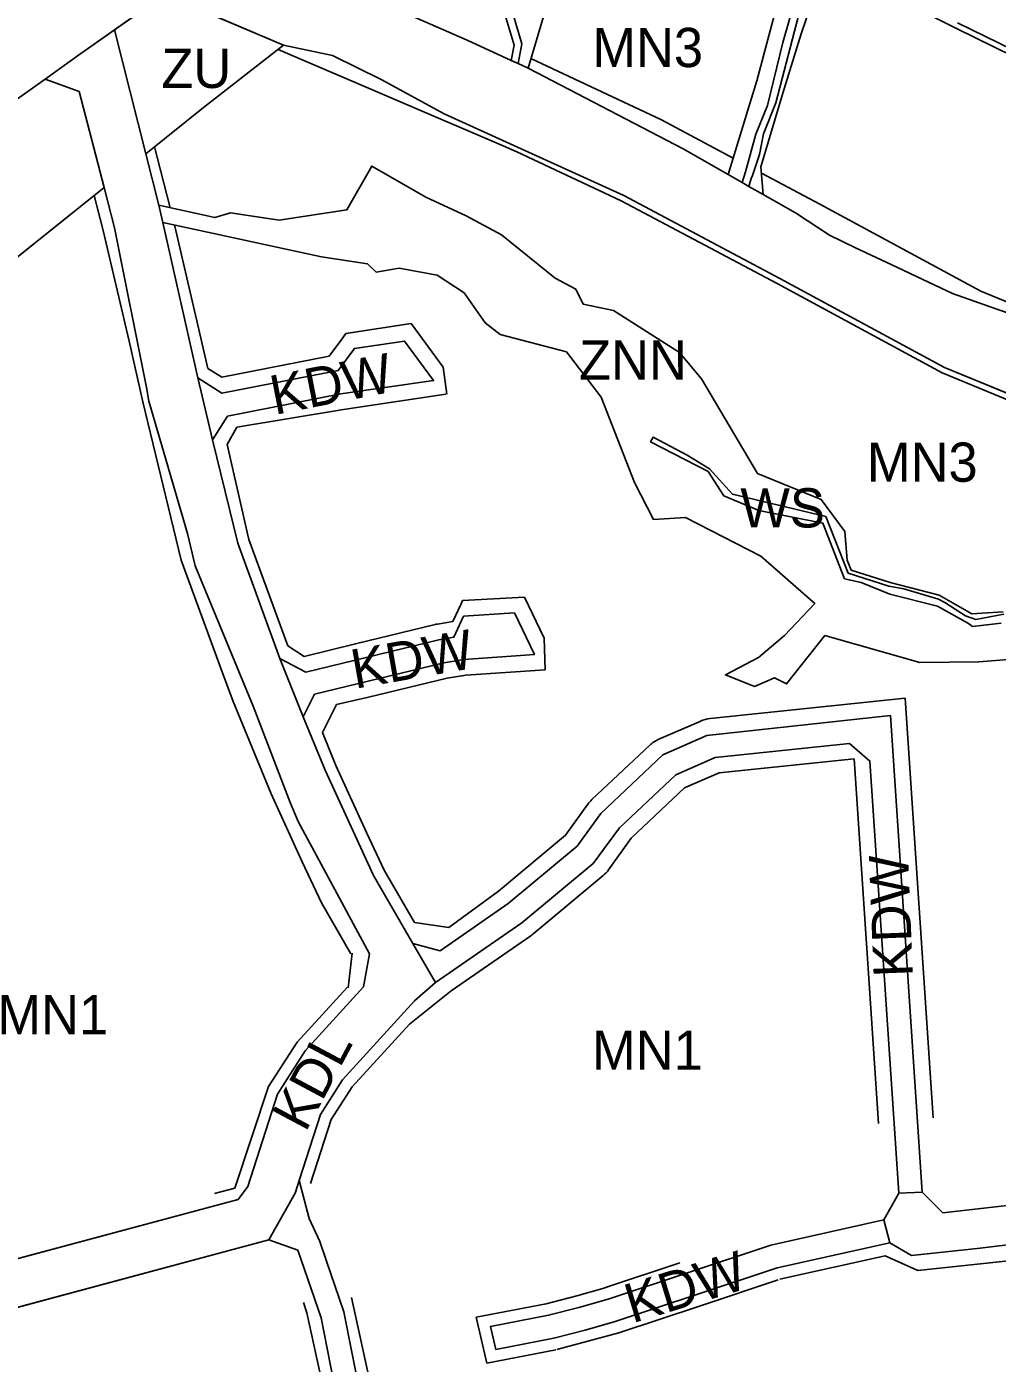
# Model space of a CAD drawing. Extents: x 7417187 to 7419415, y 5539178 to 5540826.
# Drawn here: x 7417707.9 to 7417955.3, y 5540197.8 to 5540538.4 of the extents above; entities that cross this region are included whole.
import ezdxf

# ---------------------------------------------------------------- set-up
doc = ezdxf.new("R2010")
doc.units = 0
for name, color, linetype in [('linie_rozgraniczajace', 7, 'Continuous'), ('linie_zabudowy_nieprzekraczalne', 7, 'Continuous'), ('linie_zabudowy_obowiazujace', 7, 'Continuous'), ('oznaczenia_przeznaczen', 7, 'Continuous')]:
    doc.layers.add(name, color=color, linetype=linetype)

msp = doc.modelspace()

# ---------------------------------------------------------------- linework, layer by layer
at = {"layer": 'linie_rozgraniczajace'}
for p, q in [((7417721.15, 5540531.13), (7417754.99, 5540555.17)), ((7417743.02, 5540546.67), (7417730.32, 5540537.65)), ((7417773.39, 5540533.71), (7417743.02, 5540546.67)), ((7417798.18, 5540544.56), (7417820.16, 5540535.03)), ((7417722.61, 5540532.17), (7417730.32, 5540537.65)), ((7417730.32, 5540537.65), (7417722.61, 5540532.17)), ((7417730.32, 5540537.65), (7417738.33, 5540506.03)), ((7417820.16, 5540535.03), (7417831.39, 5540529.85)), ((7417712.6, 5540525.06), (7417721.15, 5540531.13)), ((7417721.15, 5540531.13), (7417722.61, 5540532.17)), ((7417722.61, 5540532.17), (7417721.15, 5540531.13)), ((7417785.87, 5540531.06), (7417773.39, 5540533.71)), ((7417798.3, 5540524.96), (7417785.87, 5540531.06)), ((7417831.39, 5540529.85), (7417833.16, 5540529.03)), ((7417833.16, 5540529.03), (7417835.7, 5540527.85)), ((7417835.7, 5540527.85), (7417875.24, 5540507.34)), ((7417677.82, 5540500.35), (7417712.6, 5540525.06)), ((7417712.6, 5540525.06), (7417721.32, 5540521.92)), ((7417721.32, 5540521.92), (7417712.6, 5540525.06)), ((7417814.35, 5540516.24), (7417798.3, 5540524.96)), ((7417721.32, 5540521.92), (7417727.66, 5540497.43)), ((7417727.66, 5540497.43), (7417721.32, 5540521.92)), ((7417860.11, 5540495.43), (7417814.35, 5540516.24)), ((7417875.24, 5540507.34), (7417886.67, 5540500.79)), ((7417738.33, 5540506.03), (7417741.65, 5540492.92)), ((7417886.67, 5540500.79), (7417890.26, 5540498.73)), ((7417727.66, 5540497.43), (7417692.82, 5540469.59)), ((7417730.31, 5540487.2), (7417727.66, 5540497.43)), ((7417890.26, 5540498.73), (7417892, 5540497.73)), ((7417892, 5540497.73), (7417895.64, 5540495.65)), ((7417899.9, 5540474.27), (7417860.11, 5540495.43)), ((7417895.64, 5540495.65), (7417903.84, 5540490.95)), ((7417741.65, 5540492.92), (7417742.63, 5540488.53)), ((7417903.84, 5540490.95), (7417912.5, 5540485.34)), ((7417738.48, 5540446.45), (7417730.31, 5540487.2)), ((7417742.63, 5540488.53), (7417751.52, 5540448.92)), ((7417912.5, 5540485.34), (7417919.18, 5540482.07)), ((7417919.18, 5540482.07), (7417928.45, 5540477.77)), ((7417928.45, 5540477.77), (7417943.89, 5540470.43)), ((7417941.88, 5540451.55), (7417899.9, 5540474.27)), ((7417943.89, 5540470.43), (7417954.91, 5540466.53)), ((7417954.91, 5540466.53), (7417968.32, 5540461.96)), ((7417972.03, 5540439.13), (7417941.88, 5540451.55)), ((7417739.02, 5540443.03), (7417738.48, 5540446.45)), ((7417751.52, 5540448.92), (7417755.31, 5540433.16)), ((7417748.91, 5540409.28), (7417739.02, 5540443.03)), ((7417755.31, 5540433.16), (7417761.7, 5540406.83)), ((7417750.85, 5540401.04), (7417748.91, 5540409.28)), ((7417761.7, 5540406.83), (7417772.44, 5540377.44)), ((7417765.62, 5540365.27), (7417750.85, 5540401.04)), ((7417772.44, 5540377.44), (7417778.39, 5540362.54)), ((7417775.1, 5540340.73), (7417765.62, 5540365.27)), ((7417778.39, 5540362.54), (7417784, 5540348.93)), ((7417784, 5540348.93), (7417796.34, 5540322.1)), ((7417777.14, 5540335.84), (7417775.1, 5540340.73)), ((7417795.26, 5540302.11), (7417777.14, 5540335.84)), ((7417796.34, 5540322.1), (7417806.34, 5540304.78)), ((7417806.34, 5540304.78), (7417812.11, 5540294.81)), ((7417793.78, 5540293.77), (7417795.26, 5540302.11)), ((7417778.9, 5540277.39), (7417793.78, 5540293.77)), ((7417812.11, 5540294.81), (7417806.76, 5540290.13)), ((7417806.76, 5540290.13), (7417788.45, 5540270.06)), ((7417771.85, 5540266.4), (7417778.9, 5540277.39)), ((7417788.45, 5540270.06), (7417782.79, 5540261.23)), ((7417764.25, 5540242.82), (7417771.85, 5540266.4)), ((7417782.79, 5540261.23), (7417777.37, 5540244.41)), ((7417761.83, 5540239.55), (7417764.25, 5540242.82)), ((7417777.37, 5540244.41), (7417776.33, 5540241.16)), ((7417688.57, 5540219.9), (7417761.83, 5540239.55)), ((7417776.33, 5540241.16), (7417769.63, 5540229.24)), ((7417769.63, 5540229.24), (7417692.17, 5540208.43))]:
    msp.add_line(p, q, dxfattribs=at)
for points in [[(7417831.39, 5540529.85), (7417820.16, 5540535.03), (7417798.18, 5540544.56), (7417791, 5540547.66), (7417797.05, 5540552.51), (7417804.52, 5540558.84), (7417824.8, 5540558.44), (7417832.16, 5540533.76)], [(7417890.26, 5540498.73), (7417886.67, 5540500.79), (7417892, 5540518), (7417894, 5540524.6), (7417900.3, 5540548.37), (7417902.15, 5540551.62), (7417889.23, 5540551.09), (7417843.6, 5540554.5), (7417835.7, 5540527.85), (7417833.16, 5540529.03), (7417834.11, 5540534.07), (7417826.96, 5540558.39), (7417844.03, 5540555.97), (7417854.44, 5540555.19), (7417889.34, 5540552.59), (7417907.87, 5540553.35), (7417904.2, 5540546.89), (7417900.63, 5540534.39), (7417896.75, 5540518.36), (7417893.74, 5540511.02), (7417891.13, 5540501.46)], [(7417886.67, 5540500.79), (7417875.24, 5540507.34), (7417835.7, 5540527.85), (7417843.6, 5540554.5), (7417889.23, 5540551.09), (7417902.15, 5540551.62), (7417900.3, 5540548.37), (7417894, 5540524.6), (7417892, 5540518)], [(7417773.39, 5540533.71), (7417752.96, 5540517.83), (7417738.33, 5540506.03), (7417730.32, 5540537.65), (7417743.02, 5540546.67)], [(7417755.31, 5540433.16), (7417751.52, 5540448.92), (7417757.7, 5540445.03), (7417786.9, 5540450.73), (7417787.32, 5540450.79), (7417791.47, 5540456.45), (7417804.24, 5540458.29), (7417811.65, 5540448.24), (7417788.01, 5540444.83), (7417759.13, 5540439.2)], [(7417778.39, 5540362.54), (7417772.44, 5540377.44), (7417779.05, 5540373.94), (7417812.95, 5540382.19), (7417816.8, 5540382.83), (7417819.28, 5540388.19), (7417832.25, 5540389.07), (7417837.34, 5540378.44), (7417819.39, 5540377.18), (7417814.28, 5540376.34), (7417781.29, 5540368.31)], [(7417936.17, 5540241.42), (7417930.17, 5540241.16), (7417922.83, 5540351.26), (7417917.59, 5540355.73), (7417883.42, 5540352.19), (7417873.34, 5540347.79), (7417858.99, 5540334.29), (7417852.28, 5540325.15), (7417834.11, 5540310.04), (7417812.11, 5540294.81), (7417806.34, 5540304.78), (7417813.29, 5540302.94), (7417830.63, 5540314.93), (7417848.24, 5540329.6), (7417854.23, 5540337.95), (7417870.02, 5540352.89), (7417881.3, 5540357.81), (7417928.06, 5540362.89)], [(7417927.92, 5540228.51), (7417899.19, 5540222.11), (7417878.73, 5540215.32), (7417857.92, 5540208.42), (7417850.25, 5540206.23), (7417842.24, 5540204.18), (7417827.46, 5540201.31), (7417826.13, 5540207.17), (7417840.92, 5540210.04), (7417848.69, 5540212.03), (7417856.16, 5540214.15), (7417876.84, 5540221.01), (7417897.59, 5540227.9), (7417926.42, 5540234.32)], [(7417795.7, 5540155.94), (7417577.64, 5540122.76), (7417576.76, 5540134.39), (7417572.43, 5540156.87), (7417578.8, 5540158.49), (7417620.25, 5540170.49), (7417633.16, 5540175.08), (7417644.77, 5540181.84), (7417655.03, 5540190.71), (7417666.1, 5540198.14), (7417692.17, 5540208.43), (7417769.63, 5540229.24), (7417777.04, 5540226.64), (7417782.96, 5540209.35), (7417786.82, 5540189.84)]]:
    msp.add_lwpolyline(points, close=True, dxfattribs=at)
for points in [[(7417826.96, 5540558.39), (7417834.11, 5540534.07), (7417833.16, 5540529.03), (7417831.39, 5540529.85), (7417832.16, 5540533.76), (7417824.8, 5540558.44)], [(7417910.35, 5540551.35), (7417905.27, 5540536.57), (7417900.62, 5540521.49), (7417895.06, 5540502.69), (7417895.64, 5540495.65), (7417892, 5540497.73), (7417892.61, 5540499.72), (7417892.87, 5540500.54), (7417894.68, 5540505.87), (7417895.7, 5540511.16), (7417898.85, 5540519.06), (7417906.27, 5540547.49)], [(7417968.32, 5540461.96), (7417954.91, 5540466.53), (7417943.89, 5540470.43), (7417928.45, 5540477.77), (7417919.18, 5540482.07), (7417912.5, 5540485.34), (7417903.84, 5540490.95), (7417895.64, 5540495.65), (7417895.06, 5540502.69), (7417900.62, 5540521.49), (7417905.27, 5540536.57), (7417910.35, 5540551.35)], [(7417906.27, 5540547.49), (7417898.85, 5540519.06), (7417895.7, 5540511.16), (7417894.68, 5540505.87), (7417892.87, 5540500.54), (7417892.61, 5540499.72), (7417892, 5540497.73), (7417890.26, 5540498.73), (7417891.13, 5540501.46), (7417893.74, 5540511.02), (7417896.75, 5540518.36), (7417900.63, 5540534.39), (7417904.2, 5540546.89)], [(7417945.14, 5540539.44), (7417969.74, 5540527.46), (7417987.79, 5540519.1), (7418012.43, 5540507.77), (7418042.85, 5540495.44), (7418043.98, 5540494.99), (7418041.28, 5540489.53), (7418037.97, 5540487.48), (7418033.07, 5540486), (7418028.48, 5540482.4), (7418028.54, 5540482.27), (7418025.59, 5540477.67), (7418024.93, 5540472.63), (7418026.44, 5540465.3), (7418028.76, 5540461.43), (7418024.37, 5540456.87), (7418024.64, 5540461.41), (7418017.37, 5540490.07), (7418008.26, 5540488.82), (7418003.24, 5540501.47), (7417986.61, 5540509.43), (7417969.09, 5540526.11), (7417944.77, 5540538.03), (7417931.33, 5540544.79)], [(7417931.33, 5540544.79), (7417944.77, 5540538.03), (7417969.09, 5540526.11)], [(7417969.74, 5540527.46), (7417945.14, 5540539.44)], [(7417956.78, 5540389.28), (7417948.8, 5540388.78), (7417940.48, 5540393.52), (7417927.96, 5540396.81), (7417918.05, 5540399.94), (7417917.04, 5540402.49), (7417916.48, 5540409.78), (7417910.44, 5540417.96), (7417894.18, 5540424.58), (7417879.87, 5540448.7), (7417874.27, 5540455.41), (7417857.49, 5540466.1), (7417849.78, 5540467.74), (7417847.85, 5540471.57), (7417842.58, 5540474.38), (7417828.98, 5540485.38), (7417819.96, 5540490.19), (7417809.69, 5540494.95), (7417795.88, 5540502.92), (7417789.56, 5540491.76), (7417772.29, 5540489.08), (7417759.88, 5540490.95), (7417755.84, 5540489.78), (7417741.65, 5540492.92), (7417738.33, 5540506.03), (7417752.96, 5540517.83), (7417773.39, 5540533.71), (7417785.87, 5540531.06), (7417798.3, 5540524.96), (7417814.35, 5540516.24), (7417860.11, 5540495.43), (7417899.9, 5540474.27), (7417941.88, 5540451.55), (7417972.03, 5540439.13)], [(7417959.21, 5540377.27), (7417950.55, 5540376.53), (7417935.56, 5540376.42), (7417911.38, 5540383.29), (7417901.58, 5540370.93), (7417898.51, 5540372.52), (7417893.39, 5540370.31), (7417886.02, 5540373.21), (7417894.43, 5540377.66), (7417901.08, 5540383.24), (7417908.78, 5540391.44), (7417895.04, 5540403.47), (7417875.8, 5540413.35), (7417867.65, 5540412.84), (7417862.82, 5540422.24), (7417854.33, 5540444), (7417845.48, 5540455.57), (7417828.59, 5540459.95), (7417824.74, 5540462.99), (7417819.45, 5540470.59), (7417812.52, 5540475.11), (7417802.85, 5540476.85), (7417797.02, 5540475.9), (7417794.81, 5540477.95), (7417783.08, 5540479.79), (7417742.63, 5540488.53), (7417741.65, 5540492.92), (7417755.84, 5540489.78), (7417759.88, 5540490.95), (7417772.29, 5540489.08), (7417789.56, 5540491.76), (7417795.88, 5540502.92), (7417809.69, 5540494.95), (7417819.96, 5540490.19), (7417828.98, 5540485.38), (7417842.58, 5540474.38), (7417847.85, 5540471.57), (7417849.78, 5540467.74), (7417857.49, 5540466.1), (7417874.27, 5540455.41), (7417879.87, 5540448.7), (7417894.18, 5540424.58), (7417910.44, 5540417.96), (7417916.48, 5540409.78), (7417917.04, 5540402.49), (7417918.05, 5540399.94), (7417927.96, 5540396.81), (7417940.48, 5540393.52), (7417948.8, 5540388.78), (7417956.78, 5540389.28)], [(7417692.82, 5540469.59), (7417727.66, 5540497.43), (7417730.31, 5540487.2), (7417738.48, 5540446.45), (7417739.02, 5540443.03), (7417748.91, 5540409.28), (7417750.85, 5540401.04), (7417765.62, 5540365.27), (7417775.1, 5540340.73), (7417777.14, 5540335.84), (7417795.26, 5540302.11), (7417793.78, 5540293.77), (7417778.9, 5540277.39), (7417771.85, 5540266.4), (7417764.25, 5540242.82), (7417761.83, 5540239.55), (7417688.57, 5540219.9)], [(7418005.47, 5540243.42), (7417941.39, 5540236.16), (7417936.17, 5540241.42), (7417928.06, 5540362.89), (7417881.3, 5540357.81), (7417870.02, 5540352.89), (7417854.23, 5540337.95), (7417848.24, 5540329.6), (7417830.63, 5540314.93), (7417813.29, 5540302.94), (7417806.34, 5540304.78), (7417796.34, 5540322.1), (7417784, 5540348.93), (7417778.39, 5540362.54), (7417781.29, 5540368.31), (7417814.28, 5540376.34), (7417819.39, 5540377.18), (7417837.34, 5540378.44), (7417832.25, 5540389.07), (7417819.28, 5540388.19), (7417816.8, 5540382.83), (7417812.95, 5540382.19), (7417779.05, 5540373.94), (7417772.44, 5540377.44), (7417761.7, 5540406.83), (7417755.31, 5540433.16), (7417759.13, 5540439.2), (7417788.01, 5540444.83), (7417811.65, 5540448.24), (7417804.24, 5540458.29), (7417791.47, 5540456.45), (7417787.32, 5540450.79), (7417786.9, 5540450.73), (7417757.7, 5540445.03), (7417751.52, 5540448.92), (7417742.63, 5540488.53), (7417783.08, 5540479.79), (7417794.81, 5540477.95), (7417797.02, 5540475.9), (7417802.85, 5540476.85), (7417812.52, 5540475.11), (7417819.45, 5540470.59), (7417824.74, 5540462.99), (7417828.59, 5540459.95), (7417845.48, 5540455.57), (7417854.33, 5540444), (7417862.82, 5540422.24), (7417867.65, 5540412.84), (7417875.8, 5540413.35), (7417895.04, 5540403.47), (7417908.78, 5540391.44), (7417901.08, 5540383.24), (7417894.43, 5540377.66), (7417886.02, 5540373.21), (7417893.39, 5540370.31), (7417898.51, 5540372.52), (7417901.58, 5540370.93), (7417911.38, 5540383.29), (7417935.56, 5540376.42), (7417950.55, 5540376.53), (7417959.21, 5540377.27)], [(7417956.24, 5540386.4), (7417949.01, 5540385.55), (7417947.93, 5540386.34), (7417940.02, 5540390.74), (7417927.92, 5540393.77), (7417920.62, 5540396.78), (7417916.38, 5540397.74), (7417910.84, 5540411.94), (7417894.52, 5540415.14), (7417885.61, 5540418.83), (7417881.59, 5540425.04), (7417866.92, 5540432.59), (7417867.57, 5540433.8), (7417876.26, 5540429.2), (7417881.97, 5540425.77), (7417887.81, 5540419.25), (7417911.57, 5540413.56), (7417917.3, 5540399.12), (7417927.68, 5540395.85), (7417931.45, 5540395.18), (7417940.28, 5540392.54), (7417941.89, 5540391.7), (7417947.17, 5540388.27), (7417949.83, 5540387.35), (7417956.94, 5540388.72)], [(7417956.94, 5540388.72), (7417949.83, 5540387.35), (7417947.17, 5540388.27), (7417941.89, 5540391.7), (7417940.28, 5540392.54), (7417931.45, 5540395.18), (7417927.68, 5540395.85), (7417917.3, 5540399.12), (7417911.57, 5540413.56), (7417887.81, 5540419.25), (7417881.97, 5540425.77), (7417876.26, 5540429.2), (7417867.57, 5540433.8), (7417866.92, 5540432.59), (7417881.59, 5540425.04), (7417885.61, 5540418.83), (7417894.52, 5540415.14), (7417910.84, 5540411.94), (7417916.38, 5540397.74), (7417920.62, 5540396.78), (7417927.92, 5540393.77), (7417940.02, 5540390.74), (7417947.93, 5540386.34), (7417949.01, 5540385.55), (7417956.24, 5540386.4)], [(7417792.67, 5540191.18), (7417788.76, 5540210.91), (7417784.26, 5540224.09), (7417782.63, 5540228.86), (7417779.96, 5540234.71), (7417777.37, 5540244.41), (7417782.79, 5540261.23), (7417788.45, 5540270.06), (7417806.76, 5540290.13), (7417812.11, 5540294.81), (7417834.11, 5540310.04), (7417852.28, 5540325.15), (7417858.99, 5540334.29), (7417873.34, 5540347.79), (7417883.42, 5540352.19), (7417917.59, 5540355.73), (7417922.83, 5540351.26), (7417930.17, 5540241.16), (7417926.42, 5540234.32), (7417897.59, 5540227.9), (7417876.84, 5540221.01), (7417856.16, 5540214.15), (7417848.69, 5540212.03), (7417840.92, 5540210.04), (7417826.13, 5540207.17), (7417827.46, 5540201.31), (7417842.24, 5540204.18), (7417850.25, 5540206.23), (7417857.92, 5540208.42), (7417878.73, 5540215.32), (7417899.19, 5540222.11), (7417927.92, 5540228.51), (7417933.39, 5540225.24), (7417950.9, 5540227.13), (7417981.56, 5540230.85)], [(7417786.82, 5540189.84), (7417782.96, 5540209.35), (7417777.04, 5540226.64), (7417769.63, 5540229.24), (7417776.33, 5540241.16), (7417777.37, 5540244.41), (7417779.96, 5540234.71), (7417782.63, 5540228.86), (7417784.26, 5540224.09), (7417788.76, 5540210.91), (7417792.67, 5540191.18)], [(7417981.56, 5540230.85), (7417950.9, 5540227.13), (7417933.39, 5540225.24), (7417927.92, 5540228.51), (7417926.42, 5540234.32), (7417930.17, 5540241.16), (7417936.17, 5540241.42), (7417941.39, 5540236.16), (7418005.47, 5540243.42)]]:
    msp.add_lwpolyline(points, dxfattribs=at)
at = {"layer": 'linie_zabudowy_nieprzekraczalne'}
for points in [[(7417829.33, 5540508.1), (7417772.02, 5540532.64)], [(7417836.43, 5540530.3), (7417869.74, 5540514.67), (7417887.96, 5540504.94)], [(7417740.48, 5540507.77), (7417744.51, 5540492.23)], [(7418186.34, 5540286.9), (7418183.78, 5540301.6), (7418178.26, 5540313.77), (7418171.76, 5540324.53), (7418153.24, 5540345.66), (7418136.4, 5540364.51), (7418122.55, 5540377.27), (7418111.02, 5540383.3), (7418079.3, 5540391.47), (7418058.33, 5540397.52), (7418009.62, 5540423.88), (7417971.49, 5540437.73), (7417941.24, 5540450.2), (7417899.2, 5540472.95), (7417859.44, 5540494.09), (7417832.88, 5540506.56), (7417829.33, 5540508.1)], [(7417895.18, 5540501.14), (7417910.07, 5540493.22), (7417951.12, 5540471), (7417979.8, 5540459.18), (7418019.07, 5540444.92), (7418066.51, 5540419.25)], [(7417790.56, 5540302.13), (7417783.03, 5540315.15), (7417778.16, 5540325.56), (7417770.24, 5540342.96), (7417760.57, 5540366.41), (7417757.81, 5540373.73), (7417747.32, 5540402.48), (7417737.53, 5540442.84), (7417734.01, 5540458.28), (7417727.4, 5540486.48), (7417725.1, 5540495.37)], [(7417745.56, 5540487.89), (7417751.54, 5540462.34), (7417754.06, 5540451.3)], [(7417789.27, 5540460.21), (7417805.89, 5540462.8)], [(7417805.89, 5540462.8), (7417814.09, 5540451.66), (7417815.04, 5540444.8)], [(7417788.25, 5540458.82), (7417789.27, 5540460.21)], [(7417785.04, 5540454.44), (7417788.25, 5540458.82)], [(7417757.64, 5540449.1), (7417785.04, 5540454.44)], [(7417754.06, 5540451.3), (7417757.64, 5540449.1)], [(7417814.72, 5540444.75), (7417788.68, 5540440.89), (7417761.47, 5540436.33)], [(7417761.47, 5540436.33), (7417759.02, 5540431.95)], [(7417759.02, 5540431.95), (7417764.57, 5540407.71), (7417774.46, 5540380.6)], [(7417817.87, 5540389.74), (7417818.55, 5540391.21)], [(7417818.55, 5540391.21), (7417819.01, 5540392.18)], [(7417819.01, 5540392.18), (7417834.79, 5540393.04)], [(7417834.79, 5540393.04), (7417839.78, 5540382.61), (7417840.05, 5540374.55)], [(7417816.54, 5540386.85), (7417817.87, 5540389.74)], [(7417791.73, 5540381.19), (7417812.01, 5540386.08)], [(7417812.6, 5540386.2), (7417816.54, 5540386.85)], [(7417778.62, 5540377.96), (7417791.69, 5540381.18)], [(7417774.46, 5540380.6), (7417778.62, 5540377.96)], [(7417840.05, 5540374.55), (7417819.86, 5540373.2), (7417815.08, 5540372.42), (7417795.03, 5540367.58), (7417786.87, 5540365.69)], [(7417786.87, 5540365.69), (7417783.28, 5540358.55)], [(7417882.08, 5540362.11), (7417931.8, 5540367.26)], [(7417869.03, 5540356.82), (7417879.71, 5540361.48)], [(7417783.28, 5540358.55), (7417786.76, 5540350.12), (7417794.5, 5540333.1), (7417799, 5540323.49), (7417806.73, 5540310.11)], [(7417852, 5540341.45), (7417866.75, 5540355.32)], [(7417918.79, 5540351.84), (7417884.45, 5540348.28), (7417875.58, 5540344.41), (7417862.01, 5540331.65), (7417856.22, 5540323.57)], [(7417815.49, 5540308.83), (7417828.21, 5540318.11), (7417845.29, 5540332.35), (7417850.98, 5540340.28)], [(7417854.84, 5540322.08), (7417836.96, 5540307.19)], [(7417806.73, 5540310.11), (7417815.49, 5540308.83)], [(7417836.39, 5540306.75), (7417816.13, 5540292.75)], [(7417789.88, 5540293.47), (7417790.84, 5540302.29)], [(7417776.86, 5540279.6), (7417789.59, 5540293.57)], [(7417816.13, 5540292.75), (7417805.46, 5540284.25)], [(7417805.46, 5540284.25), (7417790.84, 5540268.22), (7417785.53, 5540259.94), (7417780.27, 5540243.61)], [(7417769.54, 5540268.35), (7417776.86, 5540279.6)], [(7417760.98, 5540242.43), (7417769.54, 5540268.35)], [(7417755.83, 5540241.03), (7417760.98, 5540242.43)], [(7417926.72, 5540225.17), (7417899.85, 5540219.19)], [(7417935.05, 5540221.41), (7417926.72, 5540225.17)], [(7417855.21, 5540217), (7417874.4, 5540223.37)], [(7417959.74, 5540224.09), (7417935.05, 5540221.41)], [(7417899.42, 5540219.08), (7417879.68, 5540212.47)], [(7417790.75, 5540214.55), (7417795.86, 5540190.83)], [(7417840.29, 5540212.98), (7417848.1, 5540214.97)], [(7417848.1, 5540214.98), (7417855.38, 5540217.05)], [(7417779.34, 5540210.66), (7417778.46, 5540213.25)], [(7417822.51, 5540209.52), (7417840.29, 5540212.97)], [(7417879.68, 5540212.47), (7417858.87, 5540205.57)], [(7417781.72, 5540199.81), (7417779.34, 5540210.66)], [(7417825.18, 5540197.82), (7417822.51, 5540209.52)], [(7417858.87, 5540205.57), (7417843.04, 5540201.29)], [(7417842.81, 5540201.24), (7417825.18, 5540197.82)], [(7417784.65, 5540186.28), (7417781.72, 5540199.81)]]:
    msp.add_lwpolyline(points, dxfattribs=at)
for centre, radius, start, end in [((7417813.14, 5540382.03), 4.2, 97.3885, 105.6047), ((7417791.72, 5540381.15), 0.0461, 77.4712, 130.6013), ((7417883.06, 5540353.64), 8.53, 96.6232, 113.1493), ((7417872.05, 5540349.75), 7.69, 113.1216, 133.5598), ((7417857.29, 5540335.81), 7.73, 133.1586, 144.6779), ((7417849.93, 5540328.01), 7.7, 309.6156, 324.7742), ((7417833.07, 5540311.64), 5.91, 304.1747, 311.1566)]:
    msp.add_arc(centre, radius, start, end, dxfattribs=at)
at = {"layer": 'linie_zabudowy_obowiazujace'}
for points in [[(7417931.8, 5540367.26), (7417938.94, 5540260.34)], [(7417925.04, 5540258.87), (7417918.79, 5540351.84)]]:
    msp.add_lwpolyline(points, dxfattribs=at)

# ---------------------------------------------------------------- texts
at = {"layer": 'oznaczenia_przeznaczen'}
for s, p in [('MN3', (7417852.07, 5540528.13)), ('ZU', (7417742.24, 5540522.81)), ('ZNN', (7417848.69, 5540448.46)), ('MN3', (7417922.05, 5540422.45)), ('WS', (7417889.81, 5540410.8)), ('MN1', (7417700.46, 5540281.65)), ('MN1', (7417851.99, 5540272.59))]:
    msp.add_text(s, height=10, dxfattribs=at).set_placement(p)
for s, rotation, p in [('KDW', 11.1832, (7417771.12, 5540439.46)), ('KDW', 9.9518, (7417791.57, 5540369.66)), ('KDW', 92.2906, (7417933.8, 5540296.37)), ('KDL', 61.9115, (7417778.97, 5540256.44)), ('KDW', 16.9908, (7417862.26, 5540207.94))]:
    msp.add_text(s, height=10, rotation=rotation, dxfattribs=at).set_placement(p)

doc.saveas('drawing.dxf')
